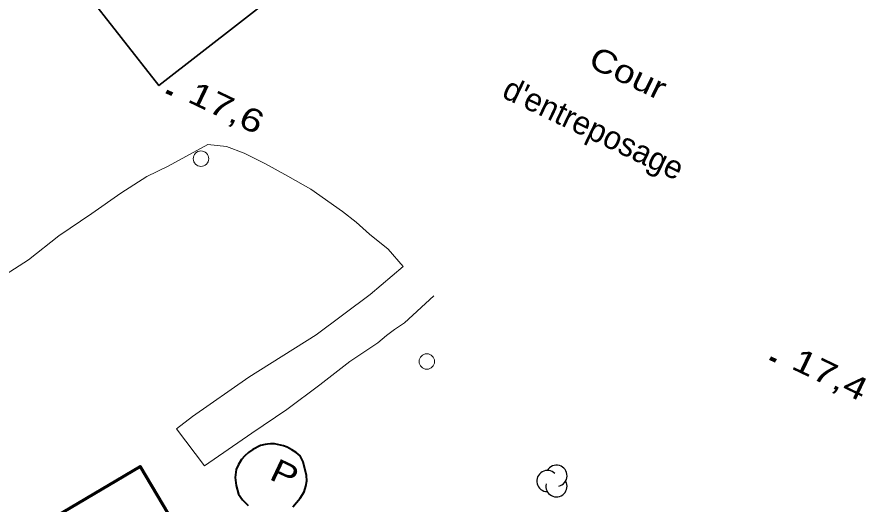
# Model space of a CAD drawing. Extents: x 355726 to 357533, y 5103782 to 5105258.
# Drawn here: x 356308.4 to 356363.5, y 5105043.5 to 5105075.2 of the extents above; entities that cross this region are included whole.
import ezdxf

# ---------------------------------------------------------------- set-up
doc = ezdxf.new("R2010")
doc.units = 0
doc.header["$LTSCALE"] = 0.6
doc.linetypes.add('LONG_DASH_SHORT_DASH', pattern=[9.9, 6, -1.2, 1.5, -1.2])
for name, color, linetype, lineweight in [('19', 7, 'Continuous', 13), ('3', 7, 'Continuous', 140), ('31', 7, 'Continuous', 35), ('36', 7, 'Continuous', 13), ('38', 7, 'Continuous', 40), ('44', 7, 'Continuous', 25), ('57', 7, 'LONG_DASH_SHORT_DASH', 13)]:
    doc.layers.add(name, color=color, linetype=linetype, lineweight=lineweight)

msp = doc.modelspace()

# ---------------------------------------------------------------- linework, layer by layer
at = {"layer": '19'}
for points in [[(356289.33, 5105039.16), (356290.33, 5105043.26), (356291.29, 5105045.4), (356292.29, 5105046.99), (356293.56, 5105048.51), (356294.91, 5105049.79), (356297.85, 5105052.01), (356300.34, 5105053.84), (356302.29, 5105055.11), (356304.94, 5105056.73), (356306.8, 5105057.86), (356309.18, 5105059.38), (356311.15, 5105060.95), (356313.29, 5105062.4), (356315.17, 5105063.72), (356316.84, 5105064.8), (356318.24, 5105065.47), (356320.8, 5105066.87)], [(356320.8, 5105066.87), (356322.01, 5105066.75), (356323.15, 5105066.31), (356324.55, 5105065.62), (356325.98, 5105064.82), (356327.48, 5105063.98), (356329.53, 5105062.53), (356330.43, 5105061.83), (356331.28, 5105061.06), (356332.5, 5105060.07), (356333.46, 5105058.95), (356331.32, 5105057.14), (356327.83, 5105054.51), (356323.45, 5105051.76), (356319.81, 5105049.21), (356318.76, 5105048.42), (356320.58, 5105046.01), (356323.65, 5105048.14), (356325.93, 5105049.67), (356328.06, 5105051.28), (356330.02, 5105052.79), (356331.82, 5105053.99), (356332.39, 5105054.47), (356332.91, 5105054.87), (356333.55, 5105055.3), (356335.45, 5105057.04)]]:
    msp.add_lwpolyline(points, dxfattribs=at)
at = {"layer": '3'}
for p, q in [((356318.12, 5105070.31), (356318.48, 5105070.14)), ((356357.27, 5105053), (356357.63, 5105052.83))]:
    msp.add_line(p, q, dxfattribs=at)
at = {"layer": '31'}
msp.add_lwpolyline([(356312.74, 5105076.96), (356323.38, 5105085.28), (356328.28, 5105079.01), (356317.63, 5105070.7), (356312.74, 5105076.96)], close=True, dxfattribs=at)
at = {"layer": '31', "lineweight": 70}
msp.add_lwpolyline([(356309.43, 5105041.84), (356316.41, 5105045.98), (356321.17, 5105037.94), (356314.46, 5105033.97), (356312.95, 5105036.51), (356311.49, 5105035.66), (356309.7, 5105038.69), (356310.88, 5105039.38), (356309.43, 5105041.84)], close=True, dxfattribs=at)
at = {"layer": '36'}
for centre in [(356320.359, 5105065.95), (356335.002, 5105052.785)]:
    msp.add_circle(centre, 0.5, dxfattribs=at)
at = {"layer": '38'}
msp.add_lwpolyline([(356326.32, 5105043.36), (356326.78, 5105043.92), (356327.04, 5105044.32), (356327.15, 5105044.7), (356327.22, 5105045.03), (356327.21, 5105045.38), (356326.98, 5105046.28), (356326.78, 5105046.66), (356326.54, 5105046.87), (356326.25, 5105047.05), (356325.95, 5105047.22), (356325.71, 5105047.31), (356325.12, 5105047.45), (356324.87, 5105047.44), (356324.68, 5105047.42), (356324.52, 5105047.39), (356324.21, 5105047.34), (356324.21, 5105047.34), (356323.72, 5105047.07), (356323.44, 5105046.88), (356323.2, 5105046.67), (356322.98, 5105046.42), (356322.8, 5105046.1), (356322.64, 5105045.77), (356322.58, 5105045.26), (356322.63, 5105044.74), (356322.8, 5105044.18), (356323.04, 5105043.8), (356323.42, 5105043.43)], dxfattribs=at)
at = {"layer": '44'}
for centre, start, end in [((356343.407, 5105045.369), 282.2692, 149.7263), ((356342.816, 5105045.026), 44.1154, 269.804), ((356343.407, 5105044.682), 166.9369, 29.6212)]:
    msp.add_arc(centre, 0.687, start, end, dxfattribs=at)

# ---------------------------------------------------------------- texts
at = {"layer": '3', "width": 1.3}
for s, p in [('17,6   ', (356319.41, 5105069.68)), ('17,4   ', (356358.55, 5105052.36))]:
    msp.add_text(s, height=1.5, rotation=334.423, dxfattribs=at).set_placement(p)
at = {"layer": '38', "width": 1.25}
msp.add_text('P', height=1.5, rotation=334.72, dxfattribs=at).set_placement((356324.71, 5105045.18))
at = {"layer": '57', "width": 1.2}
msp.add_text(' Cour ', height=1.5, rotation=334.42, dxfattribs=at).set_placement((356344.78, 5105072.25))
at = {"layer": '57'}
msp.add_text("d'entreposage", height=1.5, rotation=334.42, dxfattribs=at).set_placement((356339.79, 5105069.97))

doc.saveas('drawing.dxf')
